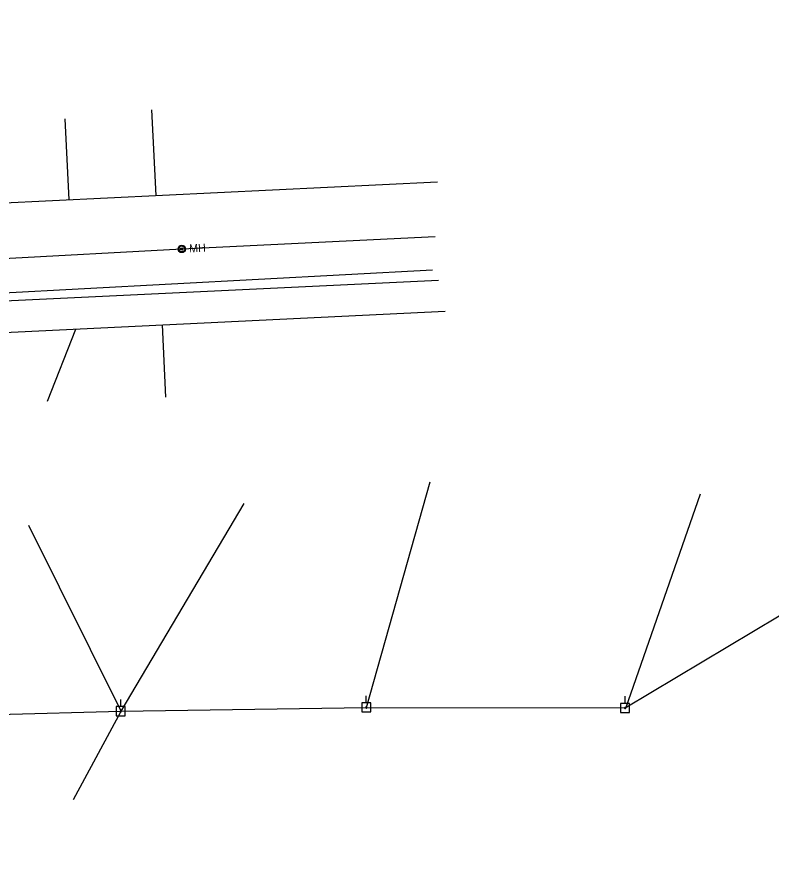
# Model space of a CAD drawing. Extents: x 600849 to 606371, y 330010 to 403088.
# Drawn here: x 605119.7 to 605425.1, y 333973.9 to 334314.3 of the extents above; entities that cross this region are included whole.
import ezdxf

# ---------------------------------------------------------------- set-up
doc = ezdxf.new("R2010")
doc.units = 0
for name, color, linetype in [('E_UTL_EPowerPole', 7, 'Continuous'), ('E_UTL_G_UG', 7, 'Continuous'), ('E_UTL_Overhead', 7, 'Continuous'), ('E_UTL_SAN_MH', 7, 'Continuous'), ('E_UTL_SAN_UG', 7, 'Continuous'), ('E_UTL_W_UG', 7, 'Continuous')]:
    doc.layers.add(name, color=color, linetype=linetype)

msp = doc.modelspace()

# ---------------------------------------------------------------- linework, layer by layer
at = {"layer": 'E_UTL_EPowerPole'}
for points in [[(605161.8, 334034.89), (605161.8, 334037.8)], [(605261.2, 334036.42), (605261.2, 334039.33)], [(605365.99, 334036.19), (605365.99, 334039.1)], [(605163.64, 334034.89), (605159.95, 334034.89)], [(605159.95, 334034.89), (605159.95, 334031.2)], [(605163.64, 334031.2), (605163.64, 334034.89)], [(605263.04, 334036.42), (605259.35, 334036.42)], [(605259.35, 334036.42), (605259.35, 334032.73)], [(605261.47, 334034.58), (605261.46, 334034.62), (605261.45, 334034.67), (605261.43, 334034.71), (605261.4, 334034.74), (605261.37, 334034.77), (605261.33, 334034.8), (605261.29, 334034.81), (605261.24, 334034.82), (605261.2, 334034.82), (605261.15, 334034.81), (605261.11, 334034.79), (605261.07, 334034.76), (605261.04, 334034.73), (605261.02, 334034.69), (605261, 334034.65), (605260.99, 334034.6), (605260.99, 334034.56), (605261, 334034.51), (605261.02, 334034.47), (605261.04, 334034.43), (605261.07, 334034.4), (605261.11, 334034.37), (605261.15, 334034.35), (605261.2, 334034.34), (605261.24, 334034.34), (605261.29, 334034.35), (605261.33, 334034.36), (605261.37, 334034.39), (605261.4, 334034.42), (605261.43, 334034.45), (605261.45, 334034.49), (605261.46, 334034.53), (605261.47, 334034.58)], [(605263.04, 334032.73), (605263.04, 334036.42)], [(605367.83, 334036.19), (605364.14, 334036.19)], [(605364.14, 334036.19), (605364.14, 334032.5)], [(605366.26, 334034.35), (605366.25, 334034.39), (605366.24, 334034.44), (605366.22, 334034.48), (605366.19, 334034.51), (605366.16, 334034.54), (605366.12, 334034.57), (605366.08, 334034.58), (605366.03, 334034.59), (605365.99, 334034.59), (605365.94, 334034.58), (605365.9, 334034.56), (605365.86, 334034.53), (605365.83, 334034.5), (605365.81, 334034.46), (605365.79, 334034.42), (605365.78, 334034.37), (605365.78, 334034.33), (605365.79, 334034.28), (605365.81, 334034.24), (605365.83, 334034.2), (605365.86, 334034.17), (605365.9, 334034.14), (605365.94, 334034.12), (605365.99, 334034.11), (605366.03, 334034.11), (605366.08, 334034.12), (605366.12, 334034.13), (605366.16, 334034.16), (605366.19, 334034.19), (605366.22, 334034.22), (605366.24, 334034.26), (605366.25, 334034.3), (605366.26, 334034.35)], [(605367.83, 334032.5), (605367.83, 334036.19)], [(605159.95, 334031.2), (605163.64, 334031.2)], [(605162.07, 334033.05), (605162.06, 334033.09), (605162.05, 334033.14), (605162.03, 334033.18), (605162, 334033.21), (605161.97, 334033.24), (605161.93, 334033.27), (605161.89, 334033.28), (605161.84, 334033.29), (605161.8, 334033.29), (605161.75, 334033.28), (605161.71, 334033.26), (605161.67, 334033.23), (605161.64, 334033.2), (605161.62, 334033.16), (605161.6, 334033.12), (605161.59, 334033.07), (605161.59, 334033.03), (605161.6, 334032.98), (605161.62, 334032.94), (605161.64, 334032.9), (605161.67, 334032.87), (605161.71, 334032.84), (605161.75, 334032.82), (605161.8, 334032.81), (605161.84, 334032.81), (605161.89, 334032.82), (605161.93, 334032.83), (605161.97, 334032.86), (605162, 334032.89), (605162.03, 334032.92), (605162.05, 334032.96), (605162.06, 334033), (605162.07, 334033.05)], [(605259.35, 334032.73), (605263.04, 334032.73)], [(605364.14, 334032.5), (605367.83, 334032.5)]]:
    msp.add_lwpolyline(points, dxfattribs=at)
at = {"layer": 'E_UTL_G_UG'}
for p, q in [((605176.07, 334241.9), (605174.36, 334276.62)), ((605140.91, 334240.17), (605139.3, 334272.95)), ((605102.33, 334238.28), (605290.02, 334247.49)), ((605095.32, 334198.25), (605290.47, 334207.64)), ((605095.32, 334198.25), (605290.47, 334207.64)), ((605052.89, 334183.33), (605293.1, 334195.11)), ((605132.09, 334158.54), (605143.55, 334187.78)), ((605180.08, 334160.18), (605178.64, 334189.5))]:
    msp.add_line(p, q, dxfattribs=at)
at = {"layer": 'E_UTL_Overhead'}
for p, q in [((605261.23, 334034.58), (605287.06, 334125.88)), ((605366.24, 334034.27), (605396.52, 334121.05)), ((605161.9, 334033.05), (605211.78, 334117.13)), ((605161.9, 334033.05), (605124.58, 334108.22)), ((605142.68, 333997.29), (605161.9, 334033.05))]:
    msp.add_line(p, q, dxfattribs=at)
msp.add_lwpolyline([(605062.13, 334030.34), (605161.83, 334033.05), (605261.23, 334034.58), (605366.02, 334034.35), (605490.67, 334108.9), (605629.26, 334192.31), (605760.16, 334289.56), (605857.09, 334357.51), (605913.37, 334539.47)], dxfattribs=at)
at = {"layer": 'E_UTL_SAN_MH'}
for radius in [1.5, 1.2, 0.45]:
    msp.add_circle((605186.5, 334220.26), radius, dxfattribs=at)
at = {"layer": 'E_UTL_SAN_UG'}
msp.add_line((604916.64, 334205.57), (605186.48, 334220.25), dxfattribs=at)
msp.add_lwpolyline([(605186.48, 334220.25), (605289.14, 334225.28)], dxfattribs=at)
at = {"layer": 'E_UTL_W_UG'}
msp.add_line((605096.59, 334201.48), (605288.08, 334211.76), dxfattribs=at)
for radius, start, end in [(4094.72, 293.47118, 313.14982), (3909.72, 292.49427, 306.0322)]:
    msp.add_arc((603570.96, 337309.26), radius, start, end, dxfattribs=at)

# ---------------------------------------------------------------- texts
at = {"layer": 'E_UTL_SAN_MH'}
msp.add_text('MH', height=3.24, rotation=3.1636, dxfattribs=at).set_placement((605189.59, 334218.81))

doc.saveas('drawing.dxf')
